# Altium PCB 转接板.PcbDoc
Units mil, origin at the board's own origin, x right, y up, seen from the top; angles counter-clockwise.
Board outline 2519.69 x 2440.94 mil, 2 copper layers (Top Layer, Bottom Layer); 36 components, 45 nets, 130 pads, 10 vias.
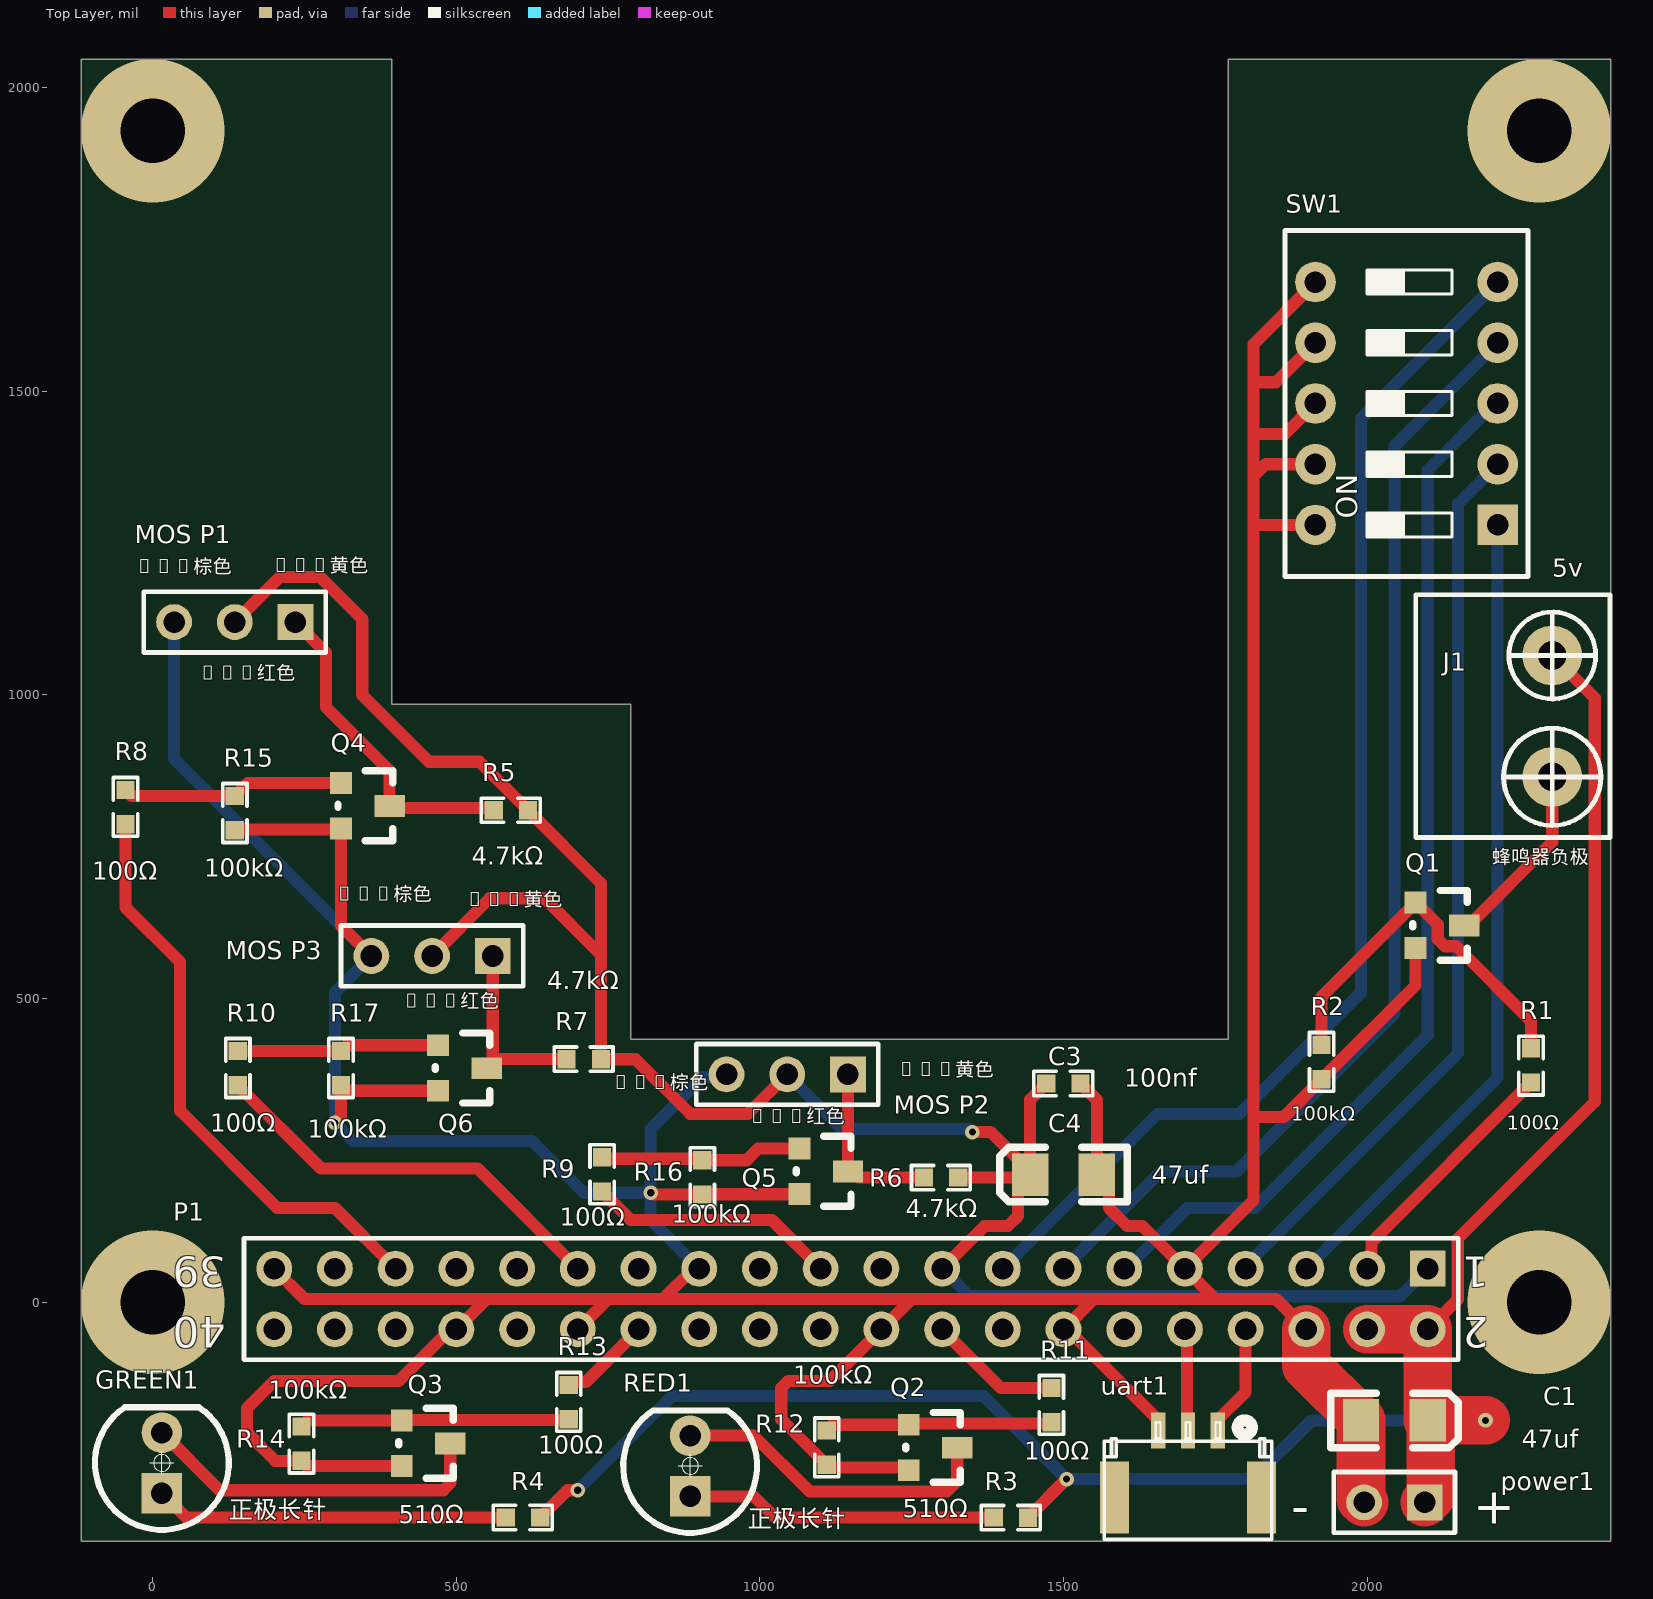
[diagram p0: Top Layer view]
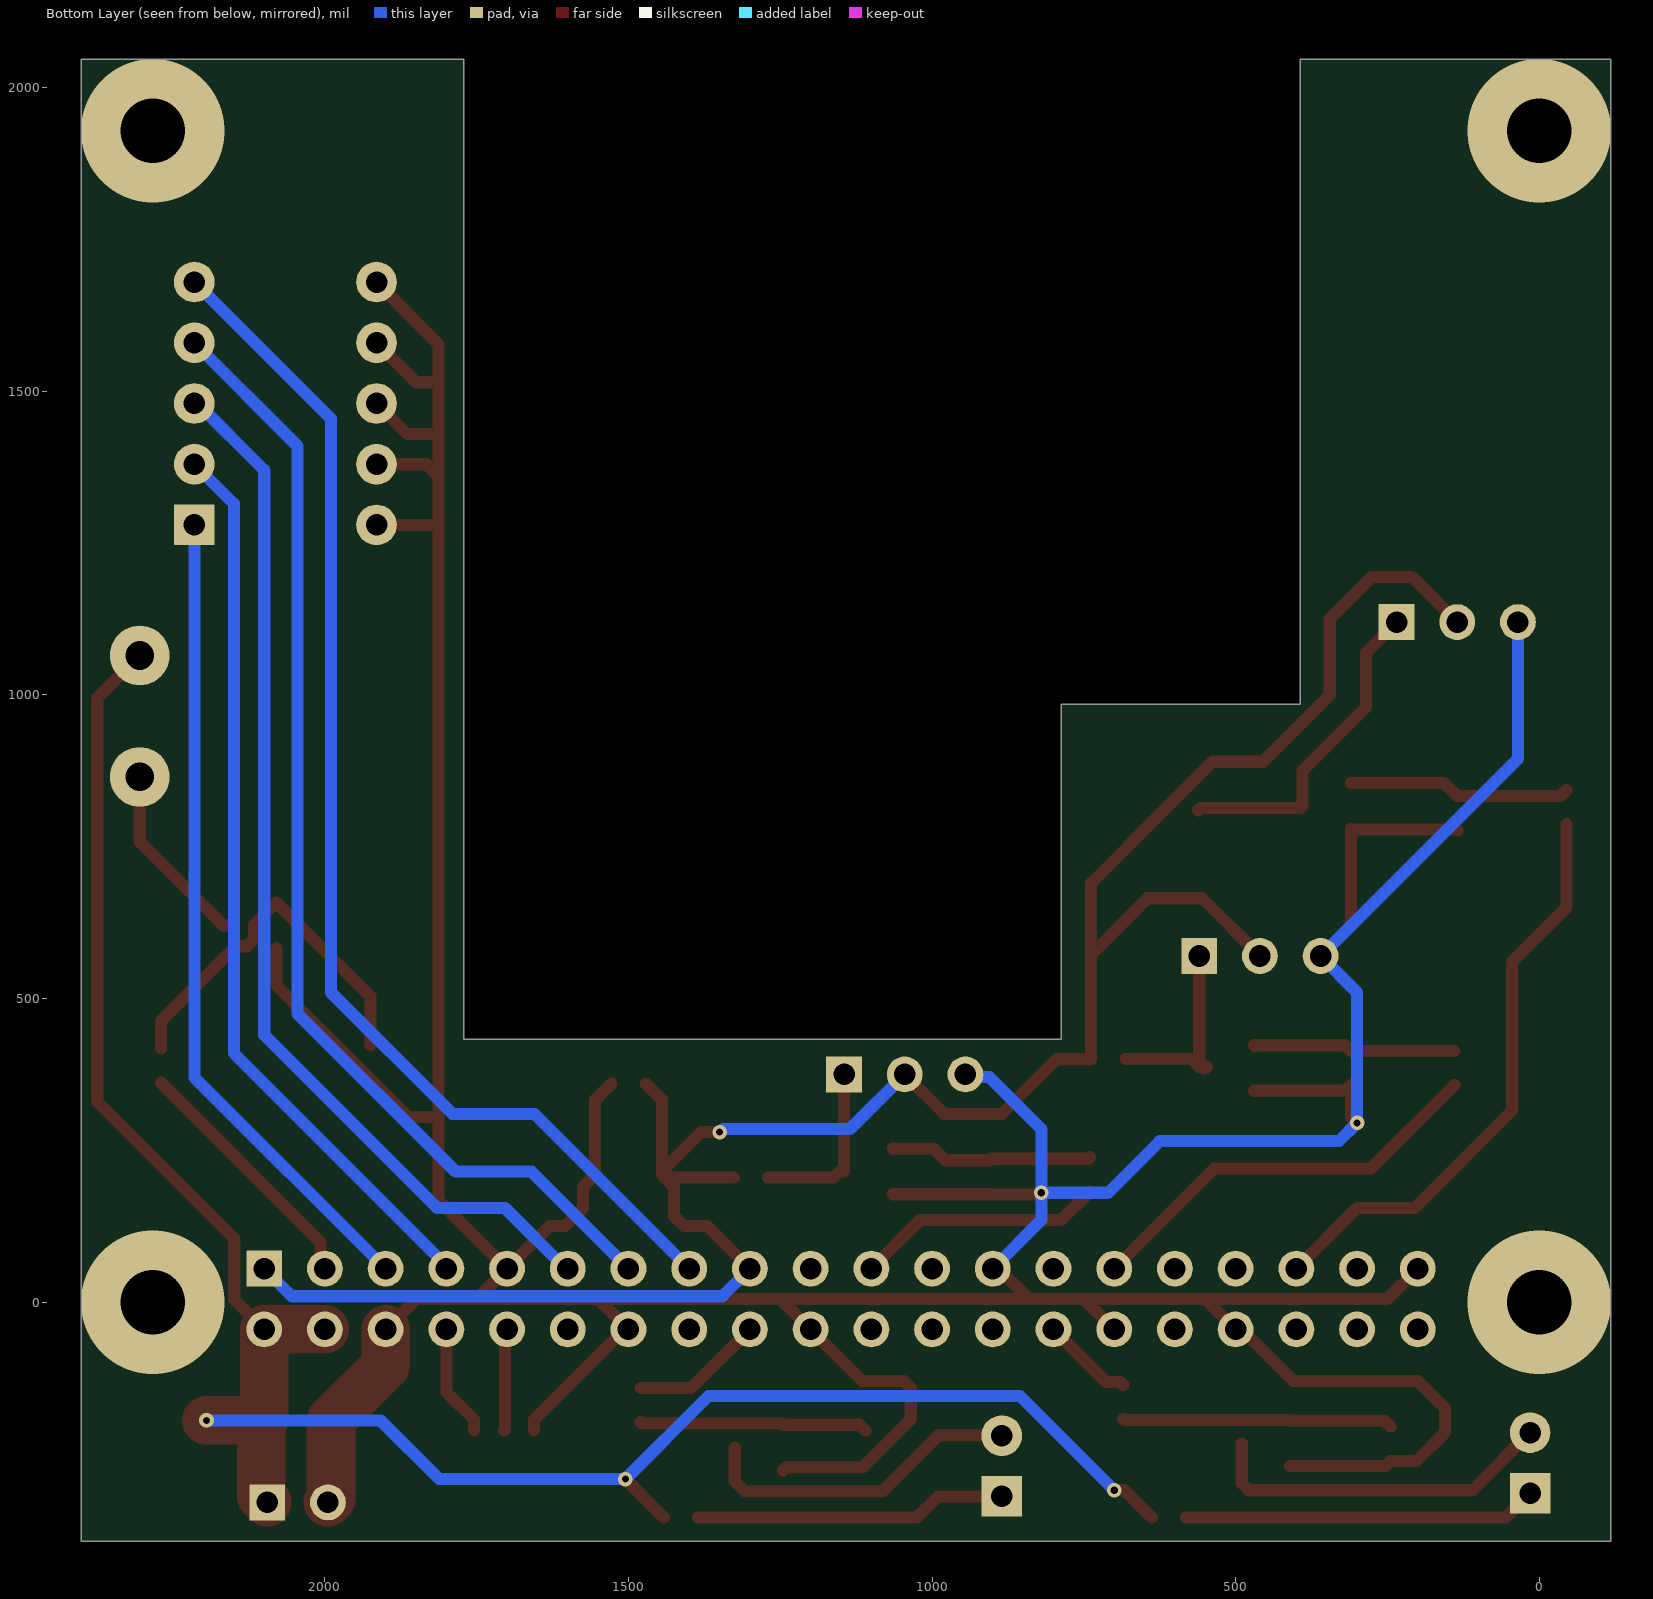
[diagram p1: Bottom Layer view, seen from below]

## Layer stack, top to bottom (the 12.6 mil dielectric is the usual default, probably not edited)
Top Solder: solder mask 0.4, Solder Resist, Dk 3.5
Top Layer: signal copper 1.4
Dielectric 1: dielectric 12.6, FR-4, Dk 4.8
Bottom Layer: signal copper 1.4
Bottom Solder: solder mask 0.4, Solder Resist, Dk 3.5

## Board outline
-118.11,-393.7 -118.11,2047.24 393.7,2047.24 393.7,984.25 787.4,984.25 787.4,433.07 1771.65,433.07 1771.65,2047.24 2401.57,2047.24 2401.57,-393.7

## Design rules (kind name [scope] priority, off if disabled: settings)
Clearance [All] p1: gap=6 ignorepadtopadclearanceinfootprint=TRUE
PolygonConnect [All] p1: connectstyle=Relief reliefconductorwidth=10 reliefentries=4 polygonreliefangle="90 Angle" airgapwidth=10
RoutingVias [All] p1: holewidth=12 width=24 viastyle="Through Hole" minholewidth=12 minwidth=24 maxholewidth=12 maxwidth=24
SolderMaskExpansion [All] p1: expansion=4 istentingtop=FALSE
Width [All] p1: maxlimit=80 minlimit=10 preferedwidth=20
30 further rules are at their usual default settings.

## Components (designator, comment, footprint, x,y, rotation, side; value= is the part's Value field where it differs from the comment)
C1 "47uF" 3216 2060,-195 r0 top
C3 "100nF" 0603P 1500,360 r180 top
C4 "47uF" 3216 1485,210 r180 top
GREEN1 "LED?" "LED 5MM-G" 15,-265 r90 top
J1 "SIP-2" 5.08接线端子2P 2305,1065 r270 top
"MOS P1" "Header 3" HDR1X3 235,1120 r180 top
"MOS P2" "Header 3" HDR1X3 1145,375 r180 top
"MOS P3" "Header 3" HDR1X3 560,570 r180 top
P1 "Header 20X2" HDR2X20 2100,55 r180 top
power1 "Battery" HDR1X2 2095,-330 r180 top
Q1 "SI2302 SOT23" SOT-23 2080,658 r270 top
Q2 "SI2302 SOT23" SOT-23 1245,-202 r270 top
Q3 "SI2302 SOT23" SOT-23 410,-195 r270 top
Q4 "SI2302 SOT23" SOT-23 310,855 r270 top
Q5 "SI2302 SOT23" SOT-23 1065,253 r270 top
Q6 "SI2302 SOT23" SOT-23 470,423 r270 top
R1 "100R" 0603P 2270,390 r270 top
R2 "100K" 0603P 1925,395 r90 top
R3 "510R" 0603P 1413.5,-355.06 r180 top
R4 "510R" 0603P 610,-355 r180 top
R5 "4.7k" 0603P 590,810 r180 top
R6 "4.7k" 0603P 1298.5,204.94 r180 top
R7 "4.7k" 0603P 710,400 r180 top
R8 "100R" 0603P -45,815 r90 top
R9 "100R" 0603P 740,210 r90 top
R10 "100R" 0603P 140,385 r90 top
R11 "100R" 0603P 1480,-170 r90 top
R12 "100K" 0603P 1110,-240 r90 top
R13 "100R" 0603P 685,-165 r90 top
R14 "100K" 0603P 244.94,-233.5 r90 top
R15 "100K" 0603P 135,805 r90 top
R16 "100K" 0603P 905,205 r90 top
R17 "100K" 0603P 310,385 r90 top
RED1 "LED?" "LED 5MM-R" 885,-270 r90 top
SW1 "5P" 拨码开关DIP-5P_G 2065,1480 r90 top
uart1 "Header 3" GH1.25-LS-3P 1705,-310 r0 top

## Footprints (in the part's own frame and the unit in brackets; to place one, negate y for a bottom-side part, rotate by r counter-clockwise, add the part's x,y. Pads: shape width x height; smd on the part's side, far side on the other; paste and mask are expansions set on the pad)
5.08接线端子2P [mm]
  round 2.5 hole 1.2: 1(0,0) 2(5.08,0)
  silkscreen extent -2.54,-5.72 7.62,2.41, body extent -2.46,-5.59 7.54,2.41, height 11
0603P [mil]
  rect 30x30 smd: 1(-28,0) 2(28.5,-0.06)
  silkscreen extent -48,-20 49,20
3216 [mil]
  rect 60x70 smd: 1(40,0) 2(-70,0)
  silkscreen extent -120,-45 90,45
GH1.25-LS-3P [mm] "A1257WR-S-3P"
  rect 1.2x3 smd: 0(-3.075,-0.3) 0(3.075,-0.3)
  rect 0.6x1.5 smd: 1(1.25,2.5) 2(0,2.5) 3(-1.25,2.5)
  silkscreen extent -3.5,-2.05 3.5,2.93, body extent -3.5,-2.15 3.5,2.25, height 4.2
HDR1X2 [mm] "Connector; Header; 2 Position"
  rect 1.5x1.5 hole 0.9: 1(0,0)
  round 1.5 hole 0.9: 2(2.54,0)
  silkscreen extent -1.27,-1.27 3.81,1.27
HDR1X3 [mm] "Connector; Header; 3 Position"
  rect 1.5x1.5 hole 0.9: 1(0,0)
  round 1.5 hole 0.9: 2(2.54,0) 3(5.08,0)
  silkscreen extent -1.27,-1.27 6.35,1.27
HDR2X20 [mm] "Connector; Header; 20x2 Position"
  rect 1.5x1.5 hole 0.9: 1(0,0)
  round 1.5 hole 0.9: 2(0,2.54) 3(2.54,0) 4(2.54,2.54) 5(5.08,0) 6(5.08,2.54) 7(7.62,0) 8(7.62,2.54) 9(10.16,0) 10(10.16,2.54) 11(12.7,0) 12(12.7,2.54) 13(15.24,0) 14(15.24,2.54) 15(17.78,0) 16(17.78,2.54) 17(20.32,0) 18(20.32,2.54) 19(22.86,0) 20(22.86,2.54) 21(25.4,0) 22(25.4,2.54) 23(27.94,0) 24(27.94,2.54) 25(30.48,0) 26(30.48,2.54) 27(33.02,0) 28(33.02,2.54) 29(35.56,0) 30(35.56,2.54) 31(38.1,0) 32(38.1,2.54) 33(40.64,0) 34(40.64,2.54) 35(43.18,0) 36(43.18,2.54) 37(45.72,0) 38(45.72,2.54) 39(48.26,0) 40(48.26,2.54)
  silkscreen extent -1.27,-1.27 49.53,3.81
"LED 5MM-G" [mm] "绿色5mm直插LED"
  rect 1.7x1.7 hole 0.9: 1(-1.27,0)
  round 1.7 hole 0.9: 2(1.27,0)
  silkscreen extent -2.8,-2.8 2.33,2.8, body extent -2.85,-2.85 2.45,2.85, height 8.75
"LED 5MM-R" [mm] "红色5mm直插LED"
  rect 1.7x1.7 hole 0.9: 1(-1.27,0)
  round 1.7 hole 0.9: 2(1.27,0)
  silkscreen extent -2.8,-2.8 2.33,2.8, body extent -2.85,-2.85 2.45,2.85, height 8.75
SOT-23 [mil]
  rect 36x36 smd: 1(0,0) 2(75,0)
  rect 36x50 smd: 3(38,80)
  silkscreen extent -20,-5 95,85
拨码开关DIP-5P_G [mm] "14.2*9.9*7mm"
  rect 1.7x1.7 hole 0.9: 1(-5.08,-3.81)
  round 1.7 hole 0.9: 2(-2.54,-3.81) 3(0,-3.81) 4(2.54,-3.81) 5(5.08,-3.81) 6(5.08,3.81) 7(2.54,3.81) 8(0,3.81) 9(-2.54,3.81) 10(-5.08,3.81)
  silkscreen extent -7.24,-5.08 7.24,5.08, body extent -7.13,-4.95 7.13,4.95, height 6.65

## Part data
C1 C4: library part CAP
C3: library part C
GREEN1 RED1: library part LED
"MOS P1" "MOS P2" "MOS P3" uart1: "Header, 3-Pin"
P1: "Header, 20-Pin, Dual row"
power1: library part "Header 2", "Header, 2-Pin"
Q1 Q2 Q3 Q4 Q5 Q6: library part NMOS
R1 R2 R3 R4 R5 R6 R7 R8 R9 R10 R11 R12 R13 R14 R15 R16 R17: library part R
SW1: library part 拨码开关5P

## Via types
v1: diameter 24, hole 12, Top Layer to Bottom Layer, tented both sides, 6 vias
v2: diameter 236.22, hole 106.3, Top Layer to Bottom Layer, tented both sides, 4 vias

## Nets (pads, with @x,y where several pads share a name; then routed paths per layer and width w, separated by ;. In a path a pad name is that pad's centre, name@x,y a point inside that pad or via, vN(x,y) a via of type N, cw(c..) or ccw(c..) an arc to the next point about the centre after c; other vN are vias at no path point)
+3V3: "MOS P1.2" "MOS P2.2" "MOS P3.2" C3.2 C4.1 P1.1 P1.17 R5.1 R6.1 R7.1 | length 3748.8
  Top Layer w20: 135,1120 209.22,1194.22 275.78,1194.22 345,1125 345,1000 455,890 538,890 R5.1 738,690 738,572 ; 460,570 555,665 645,665 738,572 ; 1045,375 980,310 885,310 795,400 R7.1 738,572 ; P1.17 1370,125 1408.28,125 1425,141.72 1425,190 C4.1@1439.94,204.94 ; R6.1 C4.1@1439.94,204.94 ; v1(1350,280) 1380,280 C4.1@1445,215 ; C3.2 1445,333.56 C4.1@1445,215 ; C4.1@1439.94,204.94 C4.1 C4.1@1445,215
  Bottom Layer w20: 1045,375 1135,285 1343.92,285 1348.92,280 v1(1350,280) ; P1.17 1345.53,9.47 2054.47,9.47 P1.1
+5V: C1.1 J1.1 P1.2 P1.4 power1.1 R3.1 R4.1 | length 3565.4
  Top Layer w20: R4.1 683,-310 v1(700,-310) ; R3.1 v1(1505,-291.56) ; P1.2 2149.35,4.35 2149.35,104.35 2375,330 2375,995 J1.1
  Top Layer w80: P1.4 P1.2 C1.1 ; power1.1 2105,-320 2105,-200 C1.1 ; v1(2195,-195) C1.1
  Bottom Layer w20: v1(700,-310) 700,-309.85 854.85,-155 1368.44,-155 v1(1505,-291.56) 1811.72,-291.56 1908.28,-195 v1(2195,-195)
BCM0: P1.27
BCM1: P1.28 R13.2 | length 152.8
  Top Layer w20: R13.2 690.06,-131.5 713.5,-131.5 P1.28
BCM2: P1.3 R1.2 | length 418.3
  Top Layer w20: P1.3 2007.47,62.47 2007.47,99.04 R1.2
BCM3: P1.5 SW1.1 | length 1355.5
  Bottom Layer w20: P1.5 2215,370 SW1.1
BCM4: P1.7 SW1.2 | length 1504
  Top Layer w20: SW1.2@2210,1385 SW1.2
  Bottom Layer w20: P1.7 1800,60 2150,410 2150,1315 SW1.2
BCM5: P1.29 R10.1 | length 685.1
  Top Layer w20: R10.1 277,220 535,220 P1.29
BCM6: P1.31
BCM7: P1.26
BCM8: P1.24
BCM9: P1.21 R9.1 | length 412.6
  Top Layer w20: R9.1 787,135 1020,135 P1.21
BCM10: P1.19
BCM11: P1.23
BCM12: P1.32
BCM13: P1.33
BCM14: P1.8 uart1.1 | length 185.5
  Top Layer w20: uart1.1 1754.21,-193.86 1800,-148.07 P1.8
BCM15: P1.10 uart1.2 | length 168.6
  Top Layer w20: P1.10 1703.19,-48.19 1703.19,-209.76 uart1.2
BCM16: P1.36
BCM17: P1.11 SW1.3 | length 1750
  Bottom Layer w20: P1.11 1603.4,55 1703.4,155 1815,155 2100,440 2100,1370 2210,1480 SW1.3
BCM18: P1.12
BCM19: P1.35 R8.1 | length 972
  Top Layer w20: R8.1 -45,650 45,560 45,315 205,155 300,155 P1.35
BCM20: P1.38
BCM21: P1.40
BCM22: P1.15 SW1.5 | length 2041.7
  Bottom Layer w20: P1.15 1655,310 1790,310 1990,510 1990,1455 SW1.5
BCM23: P1.16
BCM24: P1.18 R11.2 | length 220
  Top Layer w20: P1.18 1396.5,-141.5 R11.2
BCM25: P1.22
BCM26: P1.37 | length 10.6
  Top Layer w20: P1.37 P1.37@300,65.57
BCM27: P1.13 SW1.4 | length 1894.4
  Bottom Layer w20: P1.13 1660,215 1785,215 2045,475 2045,1410 SW1.4
GND: "MOS P1.3" "MOS P2.3" "MOS P3.3" C1.2 C3.1 C4.2 P1.6 P1.9 P1.14 P1.20 P1.25 P1.30 P1.34 P1.39 power1.2 Q1.2 Q2.2 Q3.2 Q4.2 Q5.2 Q6.2 R2.1 R12.1 R14.1 R15.1 R16.1 R17.1 SW1.6 SW1.7 SW1.8 SW1.9 SW1.10 uart1.3 | length 9802.1
  Top Layer w20: R15.1 136.5,778.5 308.5,778.5 Q4.2 310,620 360,570 ; P1.39 250,5 550,5 ; v1(300,295) 310,305 R17.1 319,348 Q6.2 ; Q3.2 253.44,-270 R14.1 201.5,-261.5 155,-215 155,-175 200,-130 405,-130 490,-45 P1.34 550,5 ; P1.30 750,5 ; v1(820,180) 823,177 R16.1 905.5,177.5 1064.5,177.5 Q5.2 ; P1.25 890,55 840,5 ; Q2.2 1240.5,-272.5 1114.5,-272.5 R12.1 1035,-193 1035,-141.72 1046.72,-130 1115,-130 P1.20 1250,5 ; C3.1 1555,333 C4.2 1575,190 1575,155 1605,125 1630,125 P1.9 ; uart1.3 1655.79,-193.86 1506.93,-45 P1.14 1550,5 ; P1.6 1850,5 1750,5 ; SW1.10 1812.72,1280 ; SW1.9 1832.72,1380 1812.72,1360 ; SW1.8 1865,1430 1812.72,1430 ; SW1.7 1850,1515 1812.72,1515 ; SW1.6 1812.72,1577.72 1812.72,1515 ; Q1.2 2080,522 R2.1 1863,305 1812.72,305 ; 550,5 750,5 ; 750,5 840,5 ; 840,5 1250,5 ; 1250,5 1550,5 ; 1550,5 1750,5 ; P1.9 1750,5 ; P1.9 1812.72,167.72 1812.72,305 ; 1812.72,305 1812.72,1280 ; 1812.72,1280 1812.72,1360 ; 1812.72,1360 1812.72,1430 ; 1812.72,1430 1812.72,1515
  Top Layer w80: P1.6 1900,-105 C1.2 1990,-325 power1.2
  Bottom Layer w20: 35,1120 35,895 360,570 300,510 v1(300,295) 330,265 625,265 710,180 v1(820,180) ; P1.25 820,135 v1(820,180) ; 945,375 940.41,370.41 905.41,370.41 820,285 v1(820,180)
NetGREEN1_1: GREEN1.1 R4.2 | length 583
  Top Layer w20: GREEN1.1 54.94,-354.94 R4.2
NetGREEN1_2: GREEN1.2 Q3.3 | length 584.5
  Top Layer w20: GREEN1.2 110,-310 478.28,-310 490,-298.28 Q3.3
NetJ1_2: J1.2 Q1.3 | length 309.2
  Top Layer w20: Q1.3 2167,620 2305,758 J1.2
"NetMOS P1_1": "MOS P1.1" Q4.3 R5.2 | length 541.6
  Top Layer w20: 235,1120 285,1070 285,980 390,875 Q4.3 393.47,813.53 558.03,813.53 R5.2
"NetMOS P2_1": "MOS P2.1" Q5.3 R6.2 | length 289.2
  Top Layer w20: 1145,375 Q5.3 1152,215 1162,205 R6.2
"NetMOS P3_1": "MOS P3.1" Q6.3 R7.2 | length 333.1
  Top Layer w20: Q6.3@547.5,387.5 Q6.3@554.5,387.5 ; Q6.3 552,385 Q6.3@554.5,387.5 ; 562.5,567.5 560,570 560,393 Q6.3@554.5,387.5 ; R7.2 572.06,400.06 559.5,387.5 Q6.3@554.5,387.5
NetQ1_1: Q1.1 R1.1 R2.2 | length 628.3
  Top Layer w20: R2.2 1925.06,503.06 Q1.1 2116.28,621.72 2116.28,598.09 2128.37,586 2147,586 2270,463 R1.1
NetQ2_1: Q2.1 R11.1 R12.2 | length 375.5
  Top Layer w20: R12.2 1119.56,-202 Q2.1 1247,-200 1478,-200 R11.1
NetQ2_3: Q2.3 RED1.2 | length 539.9
  Top Layer w20: RED1.2 990,-220 1081.72,-311.72 1308.28,-311.72 1325,-295 Q2.3
NetQ3_1: Q3.1 R13.1 R14.2 | length 445
  Top Layer w20: R14.2 255,-195 Q3.1 411,-194 684,-194 R13.1
NetQ4_1: Q4.1 R8.2 R15.2 | length 368
  Top Layer w20: R8.2 -34.94,833.5 R15.2 156.56,855 Q4.1
NetQ5_1: Q5.1 R9.2 R16.2 | length 335.8
  Top Layer w20: R9.2 742.56,236 902.56,236 R16.2 977.78,233.5 997.28,253 Q5.1 Q5.1@1064.5,252.5
NetQ6_1: Q6.1 R10.2 R17.2 | length 337.1
  Top Layer w20: R10.2 R17.2 319.56,423 Q6.1 Q6.1@467.75,420.75
NetR3_2: R3.2 RED1.1 | length 514.5
  Top Layer w20: RED1.1 990,-320 1025,-355 R3.2
pads on no net: uart1.0
copper on no net:
  other v2: 0,0 2283.46,0 0,1929.13 2283.46,1929.13

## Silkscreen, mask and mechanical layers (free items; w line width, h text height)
Top Overlay:
  text "5v" at 2305,1195 h30
  text "PWM黄色" at 195,1193.63 h40
  text "gnd棕色" at -30,1192.51 h40
  text "vcc红色" at 75,1016.66 h40
  text "蜂鸣器负极" at 2205,713.63 h40
  text "4.7kΩ" at 525,710 h50
  text "100kΩ" at 85,690.55 h50
  text "100Ω" at -100,685.55 h50
  text "gnd棕色" at 300,652.51 h40
  text "PWM黄色" at 515,643.63 h40
  text "4.7kΩ" at 650,505 h50
  text "vcc红色" at 410,476.66 h40
  text "PWM黄色" at 1225,363.63 h40
  text "100nf" at 1600,355 h30
  text "gnd棕色" at 755,342.51 h40
  text "100kΩ" at 1875,290.44 h40
  text "vcc红色" at 980,286.66 h40
  text "100Ω" at 2230,275.44 h40
  text "100Ω" at 95,270.55 h50
  text "100kΩ" at 255,260.55 h50
  text "47uf" at 1645,195 h30
  text "4.7kΩ" at 1240,130 h50
  text "100kΩ" at 855,120.55 h50
  text "100Ω" at 670,115.55 h50
  text "100kΩ" at 1055,-144.45 h50
  text "100kΩ" at 190,-169.45 h50
  text "47uf" at 2255,-240 h30
  text "100Ω" at 635,-259.45 h50
  text "100Ω" at 1435,-269.45 h50
  text "510Ω" at 1235,-364.45 h50
  text "-" at 1875,-364.99 h60
  text "+" at 2175,-365 h60
  text "正极长针" at 125.05,-365.66 h50
  text "510Ω" at 405,-374.45 h50
  text "正极长针" at 980.05,-380.66 h50
Mechanical 1:
  the board outline again, w10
